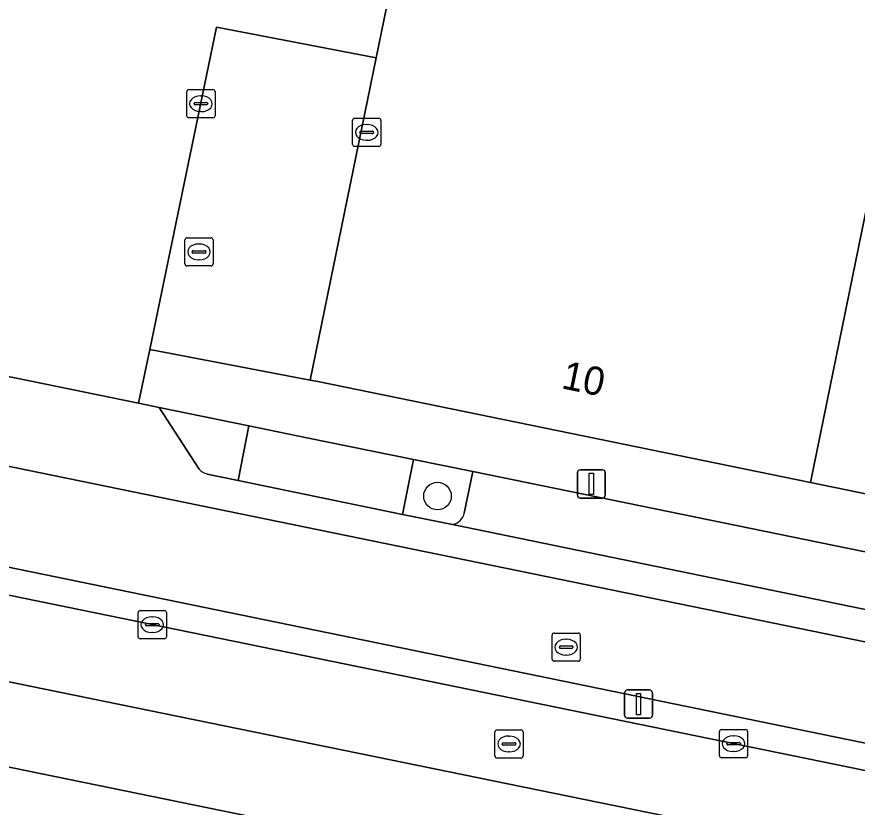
# Model space of a CAD drawing. Extents: x 157692 to 159674, y 381452 to 383291.
# Drawn here: x 158658.83 to 158688.61, y 382094.53 to 382122.55 of the extents above; entities that cross this region are included whole.
import ezdxf

# ---------------------------------------------------------------- set-up
doc = ezdxf.new("R2010")
doc.units = 0
for name, color, linetype in [('IMGEO_Berm_groen', 7, 'Continuous'), ('IMGEO_Berm_open', 7, 'Continuous'), ('IMGEO_Boom', 7, 'Continuous'), ('IMGEO_Erf', 7, 'Continuous'), ('IMGEO_Fietspad_gesloten', 7, 'Continuous'), ('IMGEO_Groenvoorziening', 7, 'Continuous'), ('IMGEO_Kolk', 7, 'Continuous'), ('IMGEO_Lichtmast', 7, 'Continuous'), ('IMGEO_Pand', 7, 'Continuous'), ('IMGEO_Pand_nummerreeks', 7, 'Continuous'), ('IMGEO_Parkeervlak_open', 7, 'Continuous'), ('IMGEO_Rijbaan_lokaal_gesloten', 7, 'Continuous'), ('IMGEO_Rijbaan_lokaal_open', 7, 'Continuous'), ('IMGEO_Rijbaan_regionaal_gesloten', 7, 'Continuous'), ('IMGEO_Rioolput', 7, 'Continuous'), ('IMGEO_Voetpad_onverhard', 7, 'Continuous'), ('IMGEO_Voetpad_open', 7, 'Continuous')]:
    doc.layers.add(name, color=color, linetype=linetype)

msp = doc.modelspace()

# ---------------------------------------------------------------- linework, layer by layer
at = {"layer": 'IMGEO_Berm_groen'}
msp.add_lwpolyline([(158771.214, 382072.861), (158638.357, 382100.078)], dxfattribs=at)
at = {"layer": 'IMGEO_Berm_open'}
msp.add_lwpolyline([(158640.25, 382105.785), (158773.962, 382078.399), (158781.033, 382076.781), (158788.955, 382074.588), (158790.901, 382074.003), (158791.317, 382075.663), (158759.226, 382082.344), (158640.458, 382106.746)], dxfattribs=at)
at = {"layer": 'IMGEO_Boom'}
msp.add_circle((158673.736, 382105.557), 0.489, dxfattribs=at)
at = {"layer": 'IMGEO_Erf'}
msp.add_lwpolyline([(158675.794, 382141.737), (158661.23, 382144.746), (158659.934, 382145.014), (158656.565, 382128.528), (158655.827, 382124.558), (158631.911, 382129.446), (158630.497, 382122.547), (158629.493, 382117.649), (158629.645, 382117.616), (158633.042, 382116.888), (158652.814, 382112.789), (158652.528, 382111.031), (158663.137, 382108.85), (158663.538, 382110.748), (158665.906, 382122.186), (158671.563, 382121.096)], close=True, dxfattribs=at)
at = {"layer": 'IMGEO_Fietspad_gesloten'}
for points in [[(158551.776, 382125.053), (158552.592, 382124.924), (158589.111, 382118.343), (158593.588, 382117.233), (158601.914, 382114.691), (158606.841, 382113.579), (158610.985, 382112.743), (158640.458, 382106.746), (158759.226, 382082.344), (158791.317, 382075.663), (158799.46, 382073.968), (158814.721, 382069.044), (158815.071, 382068.931), (158816.815, 382072.002), (158813.002, 382074.196)], [(158809.708, 382075.476), (158712.956, 382095.452), (158620.94, 382114.323)]]:
    msp.add_lwpolyline(points, dxfattribs=at)
at = {"layer": 'IMGEO_Groenvoorziening'}
for points in [[(158672.883, 382106.853), (158672.497, 382104.898), (158674.269, 382104.547)], [(158674.683, 382104.955), (158674.988, 382106.425), (158672.883, 382106.853)]]:
    msp.add_lwpolyline(points, dxfattribs=at)
msp.add_arc((158674.175, 382105.057), 0.519, 280.4955, 348.6681, dxfattribs=at)
at = {"layer": 'IMGEO_Kolk'}
for p, q in [((158664.852, 382119.042), (158664.852, 382119.894)), ((158664.927, 382119.968), (158665.779, 382119.968)), ((158665.853, 382119.894), (158665.853, 382119.042)), ((158665.34, 382119.748), (158665.365, 382119.748)), ((158665.111, 382119.462), (158665.111, 382119.474)), ((158665.549, 382119.425), (158665.151, 382119.425)), ((158665.154, 382119.511), (158665.552, 382119.511)), ((158665.595, 382119.474), (158665.595, 382119.462)), ((158665.363, 382119.188), (158665.338, 382119.188)), ((158665.779, 382118.968), (158664.927, 382118.968)), ((158670.727, 382118.025), (158670.727, 382118.877)), ((158670.802, 382118.951), (158671.654, 382118.951)), ((158671.215, 382118.731), (158671.24, 382118.731)), ((158671.728, 382118.877), (158671.728, 382118.025)), ((158670.986, 382118.445), (158670.986, 382118.457)), ((158671.424, 382118.408), (158671.026, 382118.408)), ((158671.029, 382118.494), (158671.427, 382118.494)), ((158671.47, 382118.457), (158671.47, 382118.445)), ((158671.238, 382118.171), (158671.213, 382118.171)), ((158671.654, 382117.951), (158670.802, 382117.951)), ((158663.126, 382100.571), (158663.126, 382101.423)), ((158663.201, 382101.497), (158664.053, 382101.497)), ((158664.127, 382101.423), (158664.127, 382100.571)), ((158663.614, 382101.277), (158663.639, 382101.277)), ((158663.385, 382100.991), (158663.385, 382101.003)), ((158663.823, 382100.954), (158663.425, 382100.954)), ((158663.428, 382101.04), (158663.826, 382101.04)), ((158663.869, 382101.003), (158663.869, 382100.991)), ((158663.637, 382100.717), (158663.612, 382100.717)), ((158664.053, 382100.497), (158663.201, 382100.497)), ((158683.799, 382097.278), (158684.651, 382097.278)), ((158683.724, 382096.352), (158683.724, 382097.204)), ((158684.212, 382097.058), (158684.237, 382097.058)), ((158684.725, 382097.204), (158684.725, 382096.352)), ((158683.983, 382096.772), (158683.983, 382096.784)), ((158684.421, 382096.735), (158684.023, 382096.735)), ((158684.026, 382096.821), (158684.424, 382096.821)), ((158684.467, 382096.784), (158684.467, 382096.772)), ((158684.235, 382096.498), (158684.21, 382096.498)), ((158684.651, 382096.278), (158683.799, 382096.278))]:
    msp.add_line(p, q, dxfattribs=at)
for points in [[(158664.852, 382119.042), (158664.852, 382119.894)], [(158664.927, 382119.968), (158665.779, 382119.968)], [(158665.853, 382119.894), (158665.853, 382119.042)], [(158665.779, 382118.968), (158664.927, 382118.968)], [(158670.727, 382118.025), (158670.727, 382118.877)], [(158670.802, 382118.951), (158671.654, 382118.951)], [(158671.728, 382118.877), (158671.728, 382118.025)], [(158671.654, 382117.951), (158670.802, 382117.951)], [(158663.126, 382100.571), (158663.126, 382101.423)], [(158663.201, 382101.497), (158664.053, 382101.497)], [(158664.127, 382101.423), (158664.127, 382100.571)], [(158664.053, 382100.497), (158663.201, 382100.497)], [(158683.799, 382097.278), (158684.651, 382097.278)], [(158683.724, 382096.352), (158683.724, 382097.204)], [(158684.725, 382097.204), (158684.725, 382096.352)], [(158684.651, 382096.278), (158683.799, 382096.278)]]:
    msp.add_lwpolyline(points, dxfattribs=at)
for centre, radius, start, end in [((158664.929, 382119.892), 0.0765, 91.552, 178.448), ((158664.929, 382119.892), 0.0765, 91.552, 178.448), ((158665.777, 382119.892), 0.0765, 1.552, 88.448), ((158665.777, 382119.892), 0.0765, 1.552, 88.448), ((158665.151, 382119.471), 0.0403, 85.8775, 175.7526), ((158665.148, 382119.461), 0.0366, 178.938, 274.7102), ((158665.552, 382119.468), 0.043, 264.8664, 352.4533), ((158665.556, 382119.473), 0.0386, 1.7309, 96.639), ((158664.929, 382119.044), 0.0765, 181.552, 268.448), ((158664.929, 382119.044), 0.0765, 181.552, 268.448), ((158665.777, 382119.044), 0.0765, 271.552, 358.448), ((158665.777, 382119.044), 0.0765, 271.552, 358.448), ((158670.804, 382118.875), 0.0765, 91.552, 178.448), ((158670.804, 382118.875), 0.0765, 91.552, 178.448), ((158671.652, 382118.875), 0.0765, 1.552, 88.448), ((158671.652, 382118.875), 0.0765, 1.552, 88.448), ((158671.026, 382118.454), 0.0403, 85.8775, 175.7526), ((158671.023, 382118.444), 0.0366, 178.938, 274.7102), ((158671.427, 382118.451), 0.043, 264.8664, 352.4533), ((158671.431, 382118.456), 0.0386, 1.7309, 96.639), ((158670.804, 382118.027), 0.0765, 181.552, 268.448), ((158670.804, 382118.027), 0.0765, 181.552, 268.448), ((158671.652, 382118.027), 0.0765, 271.552, 358.448), ((158671.652, 382118.027), 0.0765, 271.552, 358.448), ((158663.203, 382101.421), 0.0765, 91.552, 178.448), ((158663.203, 382101.421), 0.0765, 91.552, 178.448), ((158664.051, 382101.421), 0.0765, 1.552, 88.448), ((158664.051, 382101.421), 0.0765, 1.552, 88.448), ((158663.425, 382101), 0.0403, 85.8775, 175.7526), ((158663.422, 382100.99), 0.0366, 178.938, 274.7102), ((158663.826, 382100.997), 0.043, 264.8664, 352.4533), ((158663.83, 382101.002), 0.0386, 1.7309, 96.639), ((158663.203, 382100.573), 0.0765, 181.552, 268.448), ((158663.203, 382100.573), 0.0765, 181.552, 268.448), ((158664.051, 382100.573), 0.0765, 271.552, 358.448), ((158664.051, 382100.573), 0.0765, 271.552, 358.448), ((158683.801, 382097.202), 0.0765, 91.552, 178.448), ((158683.801, 382097.202), 0.0765, 91.552, 178.448), ((158684.649, 382097.202), 0.0765, 1.552, 88.448), ((158684.649, 382097.202), 0.0765, 1.552, 88.448), ((158684.023, 382096.781), 0.0403, 85.8775, 175.7526), ((158684.02, 382096.771), 0.0366, 178.938, 274.7102), ((158684.424, 382096.778), 0.043, 264.8664, 352.4533), ((158684.428, 382096.783), 0.0386, 1.7309, 96.639), ((158683.801, 382096.354), 0.0765, 181.552, 268.448), ((158683.801, 382096.354), 0.0765, 181.552, 268.448), ((158684.649, 382096.354), 0.0765, 271.552, 358.448), ((158684.649, 382096.354), 0.0765, 271.552, 358.448)]:
    msp.add_arc(centre, radius, start, end, dxfattribs=at)
for centre, major_axis, ratio, start_param, end_param in [((158665.339, 382119.468), (-0.387, 0.002), 0.722429, 4.712389, 7.853982), ((158665.364, 382119.468), (-0.39, 0.002), 0.717154, 1.570796, 4.712389), ((158671.214, 382118.451), (-0.387, 0.002), 0.722429, 4.712389, 7.853982), ((158671.239, 382118.451), (-0.39, 0.002), 0.717154, 1.570796, 4.712389), ((158663.613, 382100.997), (-0.387, 0.002), 0.722429, 4.712389, 7.853982), ((158663.638, 382100.997), (-0.39, 0.002), 0.717154, 1.570796, 4.712389), ((158684.211, 382096.778), (-0.387, 0.002), 0.722429, 4.712389, 7.853982), ((158684.236, 382096.778), (-0.39, 0.002), 0.717154, 1.570796, 4.712389)]:
    msp.add_ellipse(centre, major_axis=major_axis, ratio=ratio, start_param=start_param, end_param=end_param, dxfattribs=at)
at = {"layer": 'IMGEO_Lichtmast'}
for p, q in [((158678.792, 382106.488), (158679.582, 382106.488)), ((158679.582, 382106.488), (158678.792, 382106.488)), ((158678.692, 382105.588), (158678.692, 382106.388)), ((158678.692, 382106.388), (158678.692, 382105.588)), ((158679.682, 382106.388), (158679.682, 382105.588)), ((158679.682, 382105.588), (158679.682, 382106.388)), ((158679.582, 382105.488), (158678.792, 382105.488)), ((158678.792, 382105.488), (158679.582, 382105.488)), ((158680.362, 382097.781), (158680.362, 382098.581)), ((158680.362, 382098.581), (158680.362, 382097.781)), ((158680.462, 382098.681), (158681.252, 382098.681)), ((158681.252, 382098.681), (158680.462, 382098.681)), ((158681.352, 382098.581), (158681.352, 382097.781)), ((158681.352, 382097.781), (158681.352, 382098.581)), ((158681.252, 382097.681), (158680.462, 382097.681)), ((158680.462, 382097.681), (158681.252, 382097.681))]:
    msp.add_line(p, q, dxfattribs=at)
for points in [[(158679.112, 382106.363), (158679.262, 382106.363), (158679.262, 382105.613), (158679.112, 382105.613), (158679.112, 382106.363)], [(158680.782, 382098.556), (158680.932, 382098.556), (158680.932, 382097.806), (158680.782, 382097.806), (158680.782, 382098.556)]]:
    msp.add_lwpolyline(points, dxfattribs=at)
for centre, start, end in [((158678.792, 382106.388), 90, 180), ((158678.792, 382106.388), 90, 180), ((158679.582, 382106.388), 0, 90), ((158679.582, 382106.388), 360, 90), ((158678.792, 382105.588), 180, 270), ((158678.792, 382105.588), 180, 270), ((158679.582, 382105.588), 270, 0), ((158679.582, 382105.588), 270, 0), ((158680.462, 382098.581), 90, 180), ((158680.462, 382098.581), 90, 180), ((158681.252, 382098.581), 0, 90), ((158681.252, 382098.581), 360, 90), ((158680.462, 382097.781), 180, 270), ((158680.462, 382097.781), 180, 270), ((158681.252, 382097.781), 270, 0), ((158681.252, 382097.781), 270, 0)]:
    msp.add_arc(centre, 0.1, start, end, dxfattribs=at)
at = {"layer": 'IMGEO_Pand'}
for points in [[(158702.925, 382184.289), (158671.809, 382190.668), (158669.37, 382191.168), (158668.371, 382186.284), (158665.79, 382173.771), (158665.62, 382172.937), (158644.484, 382177.257), (158643.683, 382173.337), (158664.838, 382169.014), (158659.934, 382145.014), (158661.23, 382144.746), (158675.794, 382141.737), (158671.563, 382121.096), (158669.221, 382109.671), (158669.5, 382109.614), (158686.958, 382106.032)], [(158752.653, 382174.095), (158702.925, 382184.289), (158686.958, 382106.032), (158697.812, 382103.806), (158719.965, 382099.258), (158720.788, 382099.096), (158730.618, 382146.925), (158740.788, 382144.842), (158741.087, 382144.781), (158745.749, 382143.827), (158746.073, 382143.76), (158746.18, 382143.738), (158746.409, 382143.691)]]:
    msp.add_lwpolyline(points, close=True, dxfattribs=at)
at = {"layer": 'IMGEO_Parkeervlak_open'}
for points in [[(158692.401, 382101.272), (158692.698, 382102.803), (158674.988, 382106.425), (158674.683, 382104.955)], [(158674.269, 382104.547), (158692.736, 382100.743)]]:
    msp.add_lwpolyline(points, dxfattribs=at)
msp.add_arc((158674.175, 382105.057), 0.519, 280.4955, 348.6681, dxfattribs=at)
at = {"layer": 'IMGEO_Rijbaan_lokaal_gesloten'}
msp.add_lwpolyline([(158671.563, 382121.096), (158665.906, 382122.186), (158663.538, 382110.748), (158669.221, 382109.671)], close=True, dxfattribs=at)
at = {"layer": 'IMGEO_Rijbaan_lokaal_open'}
for points in [[(158665.285, 382106.51), (158663.872, 382108.691), (158663.137, 382108.85), (158652.528, 382111.031), (158652.814, 382112.789), (158633.042, 382116.888), (158629.645, 382117.616), (158629.259, 382115.706), (158620.94, 382114.323), (158712.956, 382095.452), (158809.708, 382075.476)], [(158747.563, 382093.491), (158737.882, 382095.512), (158737.459, 382093.585), (158734.967, 382092.09), (158732.747, 382092.544), (158723.335, 382094.483), (158713.507, 382096.508), (158712.292, 382096.753), (158693.837, 382100.541), (158692.736, 382100.743), (158674.269, 382104.547), (158672.497, 382104.898), (158666.671, 382106.113), (158665.579, 382106.339)]]:
    msp.add_lwpolyline(points, dxfattribs=at)
msp.add_arc((158665.685, 382106.86), 0.531, 221.153, 258.4797, dxfattribs=at)
at = {"layer": 'IMGEO_Rijbaan_regionaal_gesloten'}
for points in [[(158790.901, 382074.003), (158788.955, 382074.588), (158781.033, 382076.781), (158773.962, 382078.399), (158640.25, 382105.785), (158636.724, 382106.498), (158626.876, 382108.256), (158611.845, 382110.657), (158607.095, 382111.336), (158605.115, 382111.751), (158602.963, 382112.362), (158591.784, 382115.861)], [(158638.613, 382103.052), (158678.367, 382094.92), (158725.181, 382085.35), (158768.722, 382076.412), (158771.698, 382075.766), (158775.501, 382074.941), (158778.255, 382074.275), (158779.753, 382073.898), (158784.175, 382072.638), (158787.681, 382071.52), (158788.126, 382071.378), (158789.016, 382071.05), (158790.426, 382070.553), (158791.247, 382070.227), (158792.18, 382069.883), (158793.04, 382069.515), (158798.29, 382067.268), (158812.129, 382060.118), (158819.626, 382060.97), (158813.88, 382064.337), (158810.482, 382066.189), (158803.572, 382069.414), (158799.374, 382071.037)], [(158803.486, 382059.437), (158803.878, 382059.18), (158812.129, 382060.118), (158798.29, 382067.268), (158793.04, 382069.515), (158792.18, 382069.883), (158791.247, 382070.227), (158790.426, 382070.553), (158789.016, 382071.05), (158788.126, 382071.378), (158787.681, 382071.52), (158784.175, 382072.638), (158779.753, 382073.898), (158778.255, 382074.275), (158775.501, 382074.941), (158771.698, 382075.766), (158768.722, 382076.412), (158725.181, 382085.35), (158678.367, 382094.92), (158638.613, 382103.052)], [(158638.357, 382100.078), (158771.214, 382072.861)]]:
    msp.add_lwpolyline(points, dxfattribs=at)
at = {"layer": 'IMGEO_Rioolput'}
for p, q in [((158664.783, 382113.788), (158664.783, 382114.64)), ((158664.858, 382114.714), (158665.71, 382114.714)), ((158665.784, 382114.64), (158665.784, 382113.788)), ((158665.085, 382114.257), (158665.483, 382114.257)), ((158665.271, 382114.494), (158665.296, 382114.494)), ((158665.042, 382114.208), (158665.042, 382114.22)), ((158665.48, 382114.171), (158665.082, 382114.171)), ((158665.294, 382113.934), (158665.269, 382113.934)), ((158665.526, 382114.22), (158665.526, 382114.208)), ((158665.71, 382113.714), (158664.858, 382113.714)), ((158677.794, 382099.774), (158677.794, 382100.626)), ((158677.869, 382100.7), (158678.721, 382100.7)), ((158678.795, 382100.626), (158678.795, 382099.774)), ((158678.096, 382100.243), (158678.494, 382100.243)), ((158678.282, 382100.48), (158678.307, 382100.48)), ((158678.053, 382100.194), (158678.053, 382100.206)), ((158678.491, 382100.157), (158678.093, 382100.157)), ((158678.537, 382100.206), (158678.537, 382100.194)), ((158678.721, 382099.7), (158677.869, 382099.7)), ((158678.305, 382099.92), (158678.28, 382099.92)), ((158675.844, 382097.268), (158676.696, 382097.268)), ((158675.769, 382096.342), (158675.769, 382097.194)), ((158676.257, 382097.048), (158676.282, 382097.048)), ((158676.77, 382097.194), (158676.77, 382096.342)), ((158676.028, 382096.762), (158676.028, 382096.774)), ((158676.466, 382096.725), (158676.068, 382096.725)), ((158676.071, 382096.811), (158676.469, 382096.811)), ((158676.512, 382096.774), (158676.512, 382096.762)), ((158676.28, 382096.488), (158676.255, 382096.488)), ((158676.696, 382096.268), (158675.844, 382096.268))]:
    msp.add_line(p, q, dxfattribs=at)
for points in [[(158664.783, 382113.788), (158664.783, 382114.64)], [(158664.858, 382114.714), (158665.71, 382114.714)], [(158665.784, 382114.64), (158665.784, 382113.788)], [(158665.71, 382113.714), (158664.858, 382113.714)], [(158677.794, 382099.774), (158677.794, 382100.626)], [(158677.869, 382100.7), (158678.721, 382100.7)], [(158678.795, 382100.626), (158678.795, 382099.774)], [(158678.721, 382099.7), (158677.869, 382099.7)], [(158675.844, 382097.268), (158676.696, 382097.268)], [(158675.769, 382096.342), (158675.769, 382097.194)], [(158676.77, 382097.194), (158676.77, 382096.342)], [(158676.696, 382096.268), (158675.844, 382096.268)]]:
    msp.add_lwpolyline(points, dxfattribs=at)
for centre, radius, start, end in [((158664.86, 382114.638), 0.0765, 91.552, 178.448), ((158664.86, 382114.638), 0.0765, 91.552, 178.448), ((158665.708, 382114.638), 0.0765, 1.552, 88.448), ((158665.708, 382114.638), 0.0765, 1.552, 88.448), ((158665.082, 382114.217), 0.0403, 85.8775, 175.7526), ((158665.487, 382114.219), 0.0386, 1.7309, 96.639), ((158665.079, 382114.207), 0.0366, 178.938, 274.7102), ((158665.483, 382114.214), 0.043, 264.8664, 352.4533), ((158664.86, 382113.79), 0.0765, 181.552, 268.448), ((158664.86, 382113.79), 0.0765, 181.552, 268.448), ((158665.708, 382113.79), 0.0765, 271.552, 358.448), ((158665.708, 382113.79), 0.0765, 271.552, 358.448), ((158677.871, 382100.624), 0.0765, 91.552, 178.448), ((158677.871, 382100.624), 0.0765, 91.552, 178.448), ((158678.719, 382100.624), 0.0765, 1.552, 88.448), ((158678.719, 382100.624), 0.0765, 1.552, 88.448), ((158678.093, 382100.203), 0.0403, 85.8775, 175.7526), ((158678.498, 382100.205), 0.0386, 1.7309, 96.639), ((158678.09, 382100.193), 0.0366, 178.938, 274.7102), ((158678.494, 382100.2), 0.043, 264.8664, 352.4533), ((158677.871, 382099.776), 0.0765, 181.552, 268.448), ((158677.871, 382099.776), 0.0765, 181.552, 268.448), ((158678.719, 382099.776), 0.0765, 271.552, 358.448), ((158678.719, 382099.776), 0.0765, 271.552, 358.448), ((158675.846, 382097.192), 0.0765, 91.552, 178.448), ((158675.846, 382097.192), 0.0765, 91.552, 178.448), ((158676.694, 382097.192), 0.0765, 1.552, 88.448), ((158676.694, 382097.192), 0.0765, 1.552, 88.448), ((158676.068, 382096.771), 0.0403, 85.8775, 175.7526), ((158676.065, 382096.761), 0.0366, 178.938, 274.7102), ((158676.469, 382096.768), 0.043, 264.8664, 352.4533), ((158676.473, 382096.773), 0.0386, 1.7309, 96.639), ((158675.846, 382096.344), 0.0765, 181.552, 268.448), ((158675.846, 382096.344), 0.0765, 181.552, 268.448), ((158676.694, 382096.344), 0.0765, 271.552, 358.448), ((158676.694, 382096.344), 0.0765, 271.552, 358.448)]:
    msp.add_arc(centre, radius, start, end, dxfattribs=at)
for centre, major_axis, ratio, start_param, end_param in [((158665.27, 382114.214), (-0.387, 0.002), 0.722429, 4.712389, 7.853982), ((158665.295, 382114.214), (-0.39, 0.002), 0.717154, 1.570796, 4.712389), ((158678.281, 382100.2), (-0.387, 0.002), 0.722429, 4.712389, 7.853982), ((158678.306, 382100.2), (-0.39, 0.002), 0.717154, 1.570796, 4.712389), ((158676.256, 382096.768), (-0.387, 0.002), 0.722429, 4.712389, 7.853982), ((158676.281, 382096.768), (-0.39, 0.002), 0.717154, 1.570796, 4.712389)]:
    msp.add_ellipse(centre, major_axis=major_axis, ratio=ratio, start_param=start_param, end_param=end_param, dxfattribs=at)
at = {"layer": 'IMGEO_Voetpad_onverhard'}
for points in [[(158667.05, 382108.047), (158663.872, 382108.691), (158665.285, 382106.51)], [(158665.579, 382106.339), (158666.671, 382106.113), (158667.05, 382108.047)]]:
    msp.add_lwpolyline(points, dxfattribs=at)
msp.add_arc((158665.685, 382106.86), 0.531, 221.153, 258.4797, dxfattribs=at)
at = {"layer": 'IMGEO_Voetpad_open'}
for points in [[(158697.812, 382103.806), (158686.958, 382106.032), (158669.5, 382109.614), (158669.221, 382109.671), (158663.538, 382110.748), (158663.137, 382108.85), (158663.872, 382108.691), (158667.05, 382108.047), (158669.103, 382107.627), (158672.883, 382106.853), (158674.988, 382106.425), (158692.698, 382102.803), (158694.667, 382102.373), (158712.287, 382098.765), (158714.258, 382098.383), (158725.348, 382096.098), (158725.714, 382097.882), (158720.748, 382098.902), (158720.788, 382099.096), (158719.965, 382099.258)], [(158669.103, 382107.627), (158667.05, 382108.047), (158666.671, 382106.113), (158672.497, 382104.898), (158672.883, 382106.853)]]:
    msp.add_lwpolyline(points, close=True, dxfattribs=at)

# ---------------------------------------------------------------- texts
at = {"layer": 'IMGEO_Pand_nummerreeks'}
msp.add_text('10', height=1, rotation=348.4091, dxfattribs=at).set_placement((158678.09, 382109.383))

doc.saveas('drawing.dxf')
